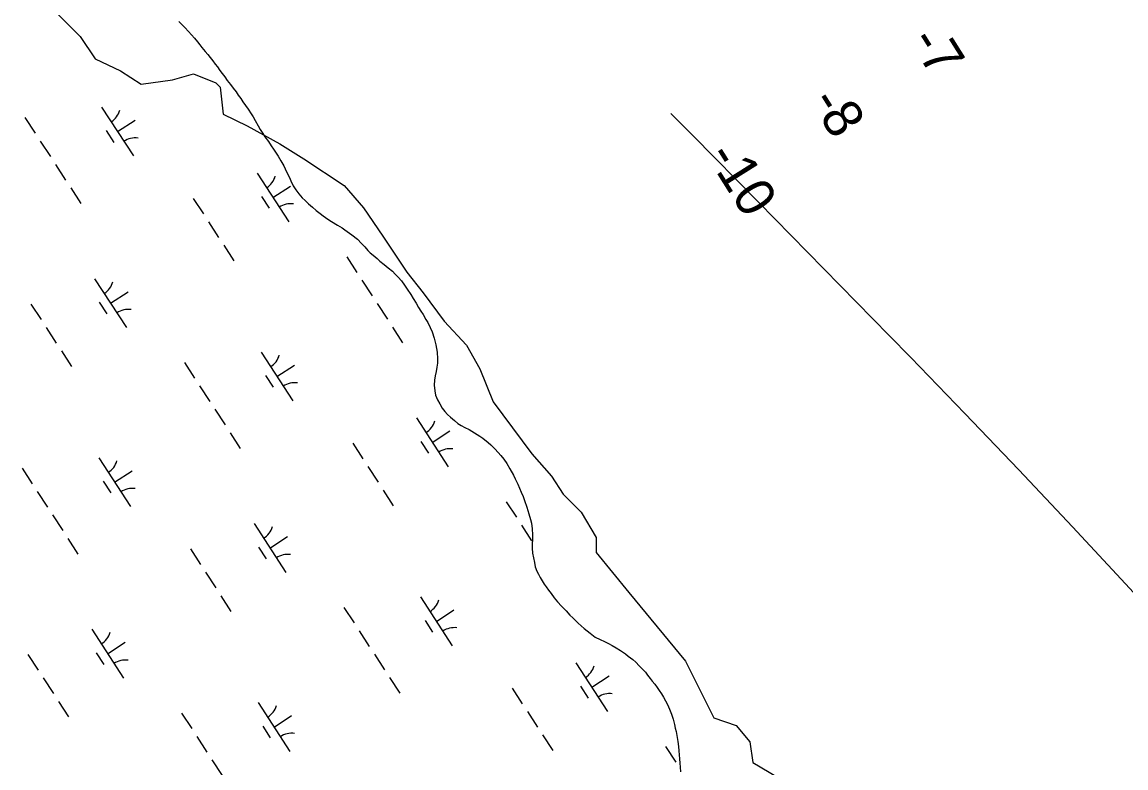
# Model space of a CAD drawing. Extents: x 3953924 to 3974542, y 193747 to 216192.
# Drawn here: x 3963057 to 3964005, y 203861 to 204501 of the extents above; entities that cross this region are included whole.
import ezdxf

# ---------------------------------------------------------------- set-up
doc = ezdxf.new("R2010")
doc.units = 0
for name, color, linetype in [('V-RIVR-EDGE', 7, 'Continuous'), ('V-RIVR-RANG', 7, 'Continuous'), ('V-TOPO-MINR', 7, 'Continuous'), ('V-WETL-SWMP', 7, 'Continuous')]:
    doc.layers.add(name, color=color, linetype=linetype)

msp = doc.modelspace()

# ---------------------------------------------------------------- linework, layer by layer
at = {"layer": 'V-RIVR-EDGE'}
msp.add_lwpolyline([(3963086.12, 204509.41), (3963106.61, 204488.92), (3963119.42, 204469.71), (3963141.19, 204459.47), (3963159.12, 204447.94), (3963186.01, 204451.79), (3963203.94, 204456.91), (3963223.15, 204449.22), (3963226.99, 204445.38), (3963229.55, 204422.33), (3963250.04, 204412.09), (3963278.22, 204396.72), (3963298.71, 204383.91), (3963333.28, 204360.86), (3963349.93, 204341.65), (3963366.58, 204317.32), (3963387.07, 204286.58), (3963401.16, 204268.65), (3963419.09, 204244.32), (3963438.3, 204223.83), (3963449.82, 204203.34), (3963461.35, 204175.17), (3963494.64, 204130.34), (3963511.29, 204111.14), (3963521.54, 204095.77), (3963536.91, 204080.4), (3963549.71, 204058.63), (3963549.71, 204045.82), (3963577.89, 204011.25), (3963626.55, 203952.34), (3963650.88, 203903.67), (3963670.09, 203897.27), (3963681.62, 203883.18), (3963684.18, 203865.25), (3963705.95, 203852.45)], dxfattribs=at)
at = {"layer": 'V-TOPO-MINR'}
msp.add_lwpolyline([(3964060.04, 203958.29), (3964004.38, 204018.74), (3963958.75, 204067.87), (3963912.83, 204116.72), (3963866.48, 204165.17), (3963819.85, 204213.34), (3963801.45, 204232.17), (3963745.33, 204289.48), (3963689.1, 204346.7), (3963632.73, 204403.76), (3963613.81, 204422.85)], dxfattribs=at)
at = {"layer": 'V-WETL-SWMP'}
for p, q in [((3963191.43, 204501.77), (3963194.12, 204499.05)), ((3963194.12, 204499.05), (3963196.45, 204496.7)), ((3963196.45, 204496.7), (3963199.63, 204493.11)), ((3963199.63, 204493.11), (3963202.33, 204490.27)), ((3963202.33, 204490.27), (3963204.78, 204487.42)), ((3963204.78, 204487.42), (3963207.35, 204484.33)), ((3963207.35, 204484.33), (3963209.3, 204481.74)), ((3963209.3, 204481.74), (3963211.26, 204479.39)), ((3963211.26, 204479.39), (3963214.08, 204475.93)), ((3963214.08, 204475.93), (3963216.28, 204473.33)), ((3963216.28, 204473.33), (3963218.24, 204470.86)), ((3963218.24, 204470.86), (3963220.68, 204467.89)), ((3963220.68, 204467.89), (3963222.52, 204465.17)), ((3963222.52, 204465.17), (3963224.47, 204462.82)), ((3963224.47, 204462.82), (3963226.67, 204459.61)), ((3963226.67, 204459.61), (3963228.63, 204457.14)), ((3963228.63, 204457.14), (3963230.83, 204454.17)), ((3963230.83, 204454.17), (3963233.03, 204451.08)), ((3963233.03, 204451.08), (3963235.73, 204447.62)), ((3963235.73, 204447.62), (3963238.17, 204444.53)), ((3963238.17, 204444.53), (3963240.49, 204441.32)), ((3963240.49, 204441.32), (3963242.45, 204438.48)), ((3963242.45, 204438.48), (3963244.53, 204435.51)), ((3963244.53, 204435.51), (3963246.36, 204432.92)), ((3963125.09, 204428.18), (3963152.37, 204386.27)), ((3963246.36, 204432.92), (3963248.68, 204429.58)), ((3963248.68, 204429.58), (3963251.01, 204426.37)), ((3963251.01, 204426.37), (3963253.45, 204422.54)), ((3963059.27, 204419.24), (3963068, 204405.83)), ((3963138.73, 204407.22), (3963153.81, 204417.04)), ((3963253.45, 204422.54), (3963255.28, 204419.82)), ((3963255.28, 204419.82), (3963256.99, 204416.73)), ((3963256.99, 204416.73), (3963259.55, 204412.29)), ((3963128.99, 204408.04), (3963135.53, 204397.99)), ((3963259.55, 204412.29), (3963261.26, 204408.96)), ((3963261.26, 204408.96), (3963263.46, 204405.5)), ((3963072.36, 204399.13), (3963081.09, 204385.72)), ((3963263.46, 204405.5), (3963265.29, 204402.66)), ((3963265.29, 204402.66), (3963268.35, 204398.58)), ((3963268.35, 204398.58), (3963270.67, 204395.12)), ((3963270.67, 204395.12), (3963272.75, 204392.03)), ((3963272.75, 204392.03), (3963274.95, 204388.69)), ((3963274.95, 204388.69), (3963276.66, 204385.98)), ((3963085.45, 204379.02), (3963094.18, 204365.61)), ((3963276.66, 204385.98), (3963279.1, 204382.15)), ((3963279.1, 204382.15), (3963281.54, 204377.7)), ((3963258.51, 204371.56), (3963285.79, 204329.66)), ((3963281.54, 204377.7), (3963283.98, 204372.77)), ((3963283.98, 204372.77), (3963286.42, 204367.83)), ((3963272.15, 204350.61), (3963287.23, 204360.43)), ((3963286.42, 204367.83), (3963287.63, 204364.99)), ((3963287.63, 204364.99), (3963289.7, 204360.67)), ((3963289.7, 204360.67), (3963291.9, 204357.09)), ((3963098.55, 204358.9), (3963107.28, 204345.49)), ((3963262.41, 204351.43), (3963268.95, 204341.37)), ((3963291.9, 204357.09), (3963294.35, 204353.63)), ((3963294.35, 204353.63), (3963297.29, 204350.41)), ((3963297.29, 204350.41), (3963299.73, 204347.94)), ((3963203.75, 204349.88), (3963212.48, 204336.47)), ((3963299.73, 204347.94), (3963302.8, 204345.21)), ((3963302.8, 204345.21), (3963306.11, 204342.24)), ((3963306.11, 204342.24), (3963309.3, 204339.52)), ((3963309.3, 204339.52), (3963312.73, 204336.79)), ((3963312.73, 204336.79), (3963315.43, 204334.81)), ((3963315.43, 204334.81), (3963319.35, 204331.96)), ((3963319.35, 204331.96), (3963322.42, 204330.1)), ((3963216.85, 204329.77), (3963225.58, 204316.36)), ((3963322.42, 204330.1), (3963327.58, 204326.99)), ((3963327.58, 204326.99), (3963331.51, 204324.63)), ((3963331.51, 204324.63), (3963333.96, 204322.9)), ((3963333.96, 204322.9), (3963339.97, 204318.68)), ((3963339.97, 204318.68), (3963344.75, 204314.71)), ((3963344.75, 204314.71), (3963348.31, 204311.13)), ((3963229.94, 204309.65), (3963238.67, 204296.25)), ((3963348.31, 204311.13), (3963351, 204308.28)), ((3963351, 204308.28), (3963353.57, 204305.19)), ((3963353.57, 204305.19), (3963355.77, 204303.09)), ((3963355.77, 204303.09), (3963358.23, 204300.98)), ((3963335.58, 204299.67), (3963344.31, 204286.26)), ((3963358.23, 204300.98), (3963361.78, 204298.13)), ((3963361.78, 204298.13), (3963363.99, 204296.03)), ((3963363.99, 204296.03), (3963367.67, 204293.05)), ((3963367.67, 204293.05), (3963371.1, 204290.2)), ((3963371.1, 204290.2), (3963374.78, 204287.23)), ((3963374.78, 204287.23), (3963377.23, 204284.88)), ((3963377.23, 204284.88), (3963379.8, 204282.16)), ((3963119.1, 204280.82), (3963146.38, 204238.91)), ((3963348.67, 204279.55), (3963357.4, 204266.15)), ((3963379.8, 204282.16), (3963382.49, 204278.94)), ((3963382.49, 204278.94), (3963385.18, 204275.36)), ((3963385.18, 204275.36), (3963387.5, 204271.9)), ((3963132.74, 204259.86), (3963147.83, 204269.68)), ((3963387.5, 204271.9), (3963390.56, 204267.21)), ((3963390.56, 204267.21), (3963392.64, 204263.87)), ((3963064.35, 204259.14), (3963073.08, 204245.73)), ((3963123, 204260.68), (3963129.55, 204250.63)), ((3963361.77, 204259.44), (3963370.49, 204246.03)), ((3963392.64, 204263.87), (3963395.2, 204259.92)), ((3963395.2, 204259.92), (3963397.27, 204256.21)), ((3963397.27, 204256.21), (3963399.11, 204253.13)), ((3963399.11, 204253.13), (3963401.06, 204250.04)), ((3963401.06, 204250.04), (3963403.5, 204245.84)), ((3963403.5, 204245.84), (3963405.09, 204243.12)), ((3963077.44, 204239.02), (3963086.17, 204225.61)), ((3963374.86, 204239.33), (3963383.59, 204225.92)), ((3963405.09, 204243.12), (3963407.28, 204239.05)), ((3963407.28, 204239.05), (3963408.87, 204235.22)), ((3963408.87, 204235.22), (3963410.69, 204229.92)), ((3963410.69, 204229.92), (3963412.13, 204224.13)), ((3963090.54, 204218.91), (3963099.26, 204205.5)), ((3963261.99, 204217.86), (3963289.27, 204175.95)), ((3963412.13, 204224.13), (3963413.09, 204217.84)), ((3963413.09, 204217.84), (3963413.55, 204211.93)), ((3963196.17, 204208.92), (3963204.9, 204195.51)), ((3963413.41, 204208.36), (3963413.02, 204205.04)), ((3963413.55, 204211.93), (3963413.41, 204208.36)), ((3963275.63, 204196.9), (3963290.72, 204206.72)), ((3963412.26, 204201.23), (3963411.38, 204197.41)), ((3963413.02, 204205.04), (3963412.26, 204201.23)), ((3963265.89, 204197.72), (3963272.44, 204187.67)), ((3963411, 204193.84), (3963410.6, 204189.41)), ((3963410.6, 204189.41), (3963411.2, 204184.61)), ((3963411.38, 204197.41), (3963411, 204193.84)), ((3963209.27, 204188.81), (3963218, 204175.4)), ((3963411.2, 204184.61), (3963411.92, 204180.91)), ((3963411.92, 204180.91), (3963413.62, 204176.84)), ((3963413.62, 204176.84), (3963415.45, 204173.51)), ((3963415.45, 204173.51), (3963417.64, 204169.56)), ((3963222.36, 204168.7), (3963231.09, 204155.29)), ((3963395.42, 204161.24), (3963422.69, 204119.34)), ((3963417.64, 204169.56), (3963419.72, 204166.96)), ((3963419.72, 204166.96), (3963422.17, 204164.36)), ((3963422.17, 204164.36), (3963424.75, 204161.89)), ((3963424.75, 204161.89), (3963428.06, 204159.04)), ((3963428.06, 204159.04), (3963431, 204156.44)), ((3963431, 204156.44), (3963433.82, 204154.82)), ((3963433.82, 204154.82), (3963437.01, 204153.08)), ((3963437.01, 204153.08), (3963440.7, 204151.22)), ((3963440.7, 204151.22), (3963445.36, 204148.61)), ((3963235.45, 204148.58), (3963244.18, 204135.17)), ((3963409.05, 204140.29), (3963424.14, 204150.11)), ((3963445.36, 204148.61), (3963449.78, 204145.75)), ((3963449.78, 204145.75), (3963452.48, 204143.89)), ((3963452.48, 204143.89), (3963456.9, 204140.3)), ((3963340.66, 204139.56), (3963349.39, 204126.15)), ((3963399.31, 204141.11), (3963405.86, 204131.05)), ((3963456.9, 204140.3), (3963459.22, 204138.2)), ((3963459.22, 204138.2), (3963462.65, 204134.73)), ((3963462.65, 204134.73), (3963465.71, 204131.52)), ((3963122.59, 204127.11), (3963149.87, 204085.21)), ((3963465.71, 204131.52), (3963467.92, 204128.92)), ((3963467.92, 204128.92), (3963470.49, 204125.83)), ((3963470.49, 204125.83), (3963473.06, 204122.12)), ((3963056.77, 204118.18), (3963065.5, 204104.77)), ((3963136.23, 204106.16), (3963151.31, 204115.98)), ((3963353.75, 204119.45), (3963362.48, 204106.04)), ((3963473.06, 204122.12), (3963475.74, 204117.55)), ((3963475.74, 204117.55), (3963478.67, 204112.24)), ((3963126.49, 204106.98), (3963133.04, 204096.92)), ((3963478.67, 204112.24), (3963480.25, 204108.91)), ((3963480.25, 204108.91), (3963482.57, 204104.34)), ((3963482.57, 204104.34), (3963485.37, 204097.56)), ((3963069.86, 204098.07), (3963078.59, 204084.66)), ((3963366.85, 204099.33), (3963375.57, 204085.93)), ((3963485.37, 204097.56), (3963487.07, 204093.73)), ((3963472.49, 204089.35), (3963481.21, 204075.94)), ((3963487.07, 204093.73), (3963488.16, 204090.4)), ((3963488.16, 204090.4), (3963490.23, 204084.73)), ((3963490.23, 204084.73), (3963492.04, 204078.81)), ((3963082.96, 204077.95), (3963091.69, 204064.54)), ((3963492.04, 204078.81), (3963493.37, 204074)), ((3963256.01, 204070.5), (3963283.29, 204028.59)), ((3963485.58, 204069.23), (3963494.31, 204055.83)), ((3963493.37, 204074), (3963494.1, 204071.04)), ((3963494.1, 204071.04), (3963494.69, 204065.99)), ((3963494.69, 204065.99), (3963495.15, 204060.82)), ((3963096.05, 204057.84), (3963104.78, 204044.43)), ((3963269.65, 204049.54), (3963284.74, 204059.36)), ((3963495.01, 204057.25), (3963494.74, 204052.82)), ((3963495.15, 204060.82), (3963495.01, 204057.25)), ((3963201.26, 204048.82), (3963209.98, 204035.41)), ((3963259.91, 204050.36), (3963266.46, 204040.31)), ((3963494.74, 204052.82), (3963494.73, 204049.37)), ((3963494.73, 204049.37), (3963495.2, 204045.18)), ((3963495.2, 204045.18), (3963495.91, 204041.11)), ((3963495.91, 204041.11), (3963496.76, 204037.17)), ((3963496.76, 204037.17), (3963497.35, 204033.47)), ((3963214.35, 204028.7), (3963223.08, 204015.29)), ((3963497.35, 204033.47), (3963498.69, 204029.77)), ((3963498.69, 204029.77), (3963500.15, 204027.06)), ((3963500.15, 204027.06), (3963501.62, 204024.22)), ((3963501.62, 204024.22), (3963503.33, 204021.38)), ((3963503.33, 204021.38), (3963505.04, 204018.66)), ((3963505.04, 204018.66), (3963506.75, 204016.19)), ((3963506.75, 204016.19), (3963508.83, 204013.47)), ((3963508.83, 204013.47), (3963511.03, 204010.5)), ((3963511.03, 204010.5), (3963513.72, 204006.92)), ((3963227.44, 204008.59), (3963236.17, 203995.18)), ((3963398.9, 204007.54), (3963426.18, 203965.63)), ((3963513.72, 204006.92), (3963516.65, 204003.21)), ((3963516.65, 204003.21), (3963520.08, 203999.5)), ((3963520.08, 203999.5), (3963523.88, 203995.54)), ((3963333.08, 203998.6), (3963341.81, 203985.19)), ((3963412.54, 203986.58), (3963427.63, 203996.4)), ((3963523.88, 203995.54), (3963527.19, 203991.95)), ((3963527.19, 203991.95), (3963529.76, 203989.48)), ((3963402.8, 203987.4), (3963409.35, 203977.35)), ((3963529.76, 203989.48), (3963534.41, 203984.9)), ((3963534.41, 203984.9), (3963539.32, 203980.57)), ((3963539.32, 203980.57), (3963544.47, 203976.35)), ((3963116.61, 203979.75), (3963143.88, 203937.85)), ((3963346.17, 203978.49), (3963354.9, 203965.08)), ((3963544.47, 203976.35), (3963549, 203973.13)), ((3963549, 203973.13), (3963553.06, 203971.02)), ((3963553.06, 203971.02), (3963556.99, 203969.15)), ((3963130.25, 203958.8), (3963145.33, 203968.62)), ((3963556.99, 203969.15), (3963560.3, 203967.53)), ((3963560.3, 203967.53), (3963563.5, 203965.92)), ((3963563.5, 203965.92), (3963566.93, 203963.93)), ((3963566.93, 203963.93), (3963570.74, 203961.45)), ((3963570.74, 203961.45), (3963574.91, 203958.72)), ((3963061.85, 203958.07), (3963070.58, 203944.66)), ((3963120.51, 203959.62), (3963127.05, 203949.56)), ((3963359.27, 203958.38), (3963368, 203944.97)), ((3963574.91, 203958.72), (3963577.36, 203956.73)), ((3963577.36, 203956.73), (3963581.16, 203953.76)), ((3963581.16, 203953.76), (3963583.86, 203951.41)), ((3963532.32, 203950.92), (3963559.6, 203909.02)), ((3963583.86, 203951.41), (3963586.8, 203948.44)), ((3963586.8, 203948.44), (3963589.62, 203945.47)), ((3963589.62, 203945.47), (3963592.07, 203942.87)), ((3963592.07, 203942.87), (3963593.9, 203940.4)), ((3963074.94, 203937.96), (3963083.67, 203924.55)), ((3963372.36, 203938.26), (3963381.09, 203924.85)), ((3963545.96, 203929.97), (3963561.05, 203939.79)), ((3963593.9, 203940.4), (3963596.1, 203937.56)), ((3963596.1, 203937.56), (3963597.94, 203935.08)), ((3963597.94, 203935.08), (3963600.02, 203932.73)), ((3963477.57, 203929.24), (3963486.3, 203915.83)), ((3963536.22, 203930.79), (3963542.77, 203920.73)), ((3963600.02, 203932.73), (3963602.22, 203929.77)), ((3963602.22, 203929.77), (3963603.81, 203927.17)), ((3963603.81, 203927.17), (3963605.89, 203924.21)), ((3963605.89, 203924.21), (3963607.6, 203921.49)), ((3963088.04, 203917.85), (3963096.77, 203904.44)), ((3963259.5, 203916.79), (3963286.77, 203874.89)), ((3963607.6, 203921.49), (3963609.3, 203918.4)), ((3963609.3, 203918.4), (3963610.89, 203915.2)), ((3963610.89, 203915.2), (3963612.71, 203911.12)), ((3963193.68, 203907.86), (3963202.41, 203894.45)), ((3963273.14, 203895.84), (3963288.22, 203905.66)), ((3963490.66, 203909.13), (3963499.39, 203895.72)), ((3963612.71, 203911.12), (3963614.54, 203906.8)), ((3963614.54, 203906.8), (3963615.87, 203902.49)), ((3963263.4, 203896.66), (3963269.94, 203886.6)), ((3963615.87, 203902.49), (3963617.08, 203897.93)), ((3963617.08, 203897.93), (3963617.68, 203894.97)), ((3963206.77, 203887.75), (3963215.5, 203874.34)), ((3963503.75, 203889.01), (3963512.48, 203875.61)), ((3963617.68, 203894.97), (3963618.53, 203891.89)), ((3963618.53, 203891.89), (3963619.36, 203886.96)), ((3963619.36, 203886.96), (3963619.96, 203883.26)), ((3963609.39, 203879.03), (3963618.12, 203865.62)), ((3963619.96, 203883.26), (3963620.55, 203879.07)), ((3963620.55, 203879.07), (3963620.78, 203875.38)), ((3963219.86, 203867.63), (3963228.59, 203854.22)), ((3963620.78, 203875.38), (3963621.01, 203872.05)), ((3963621.01, 203872.05), (3963621.36, 203868.6)), ((3963621.36, 203868.6), (3963621.59, 203864.66)), ((3963621.59, 203864.66), (3963621.94, 203861.21)), ((3963621.94, 203861.21), (3963622.04, 203857.4))]:
    msp.add_line(p, q, dxfattribs=at)
for centre, start, end in [((3963123.86, 204430.5), 302.29009, 343.83375), ((3963153.99, 204384.2), 82.29009, 123.83375), ((3963257.28, 204373.89), 302.29009, 343.83375), ((3963287.42, 204327.59), 82.29009, 123.83375), ((3963117.87, 204283.14), 302.29009, 343.83375), ((3963148.01, 204236.84), 82.29009, 123.83375), ((3963260.76, 204220.18), 302.29009, 343.83375), ((3963290.9, 204173.88), 82.29009, 123.83375), ((3963394.18, 204163.57), 302.29009, 343.83375), ((3963424.32, 204117.27), 82.29009, 123.83375), ((3963121.36, 204129.44), 302.29009, 343.83375), ((3963151.5, 204083.14), 82.29009, 123.83375), ((3963254.78, 204072.82), 302.29009, 343.83375), ((3963284.92, 204026.52), 82.29009, 123.83375), ((3963397.67, 204009.86), 302.29009, 343.83375), ((3963427.81, 203963.56), 82.29009, 123.83375), ((3963115.38, 203982.08), 302.29009, 343.83375), ((3963145.51, 203935.78), 82.29009, 123.83375), ((3963531.09, 203953.25), 302.29009, 343.83375), ((3963561.23, 203906.95), 82.29009, 123.83375), ((3963258.27, 203919.12), 302.29009, 343.83375), ((3963288.4, 203872.82), 82.29009, 123.83375)]:
    msp.add_arc(centre, 17.62, start, end, dxfattribs=at)

# ---------------------------------------------------------------- texts
at = {"layer": 'V-RIVR-RANG'}
for s, p in [('-7', (3963818.27, 204485.04)), ('-8', (3963732.93, 204432.9)), ('-10', (3963644.05, 204386.19))]:
    msp.add_text(s, height=33.5, rotation=302.16808, dxfattribs=at).set_placement(p)

doc.saveas('drawing.dxf')
